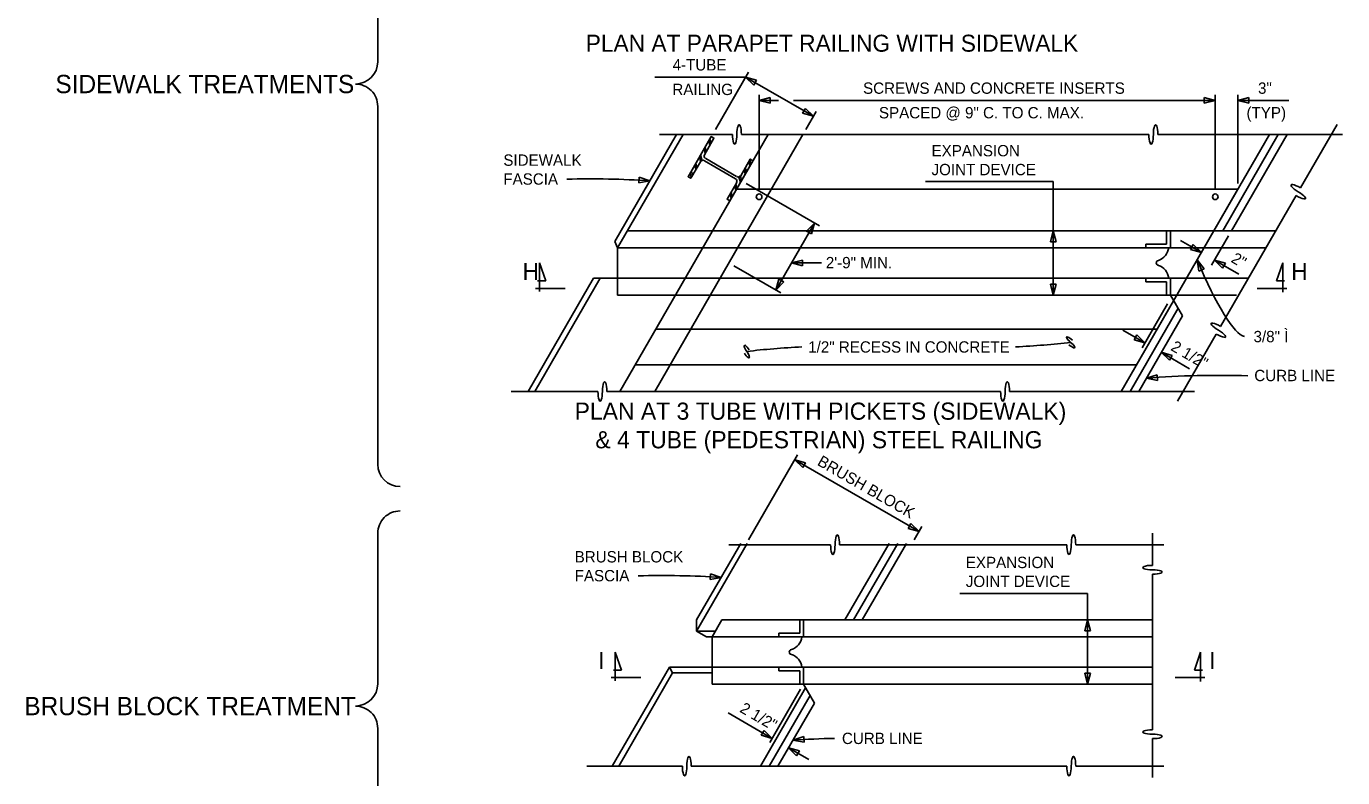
# Model space of a CAD drawing. Extents: x 19590 to 20151, y 19944 to 20103.
# Drawn here: x 19792.8 to 19846.6, y 20034 to 20064.6 of the extents above; entities that cross this region are included whole.
import ezdxf

# ---------------------------------------------------------------- set-up
doc = ezdxf.new("R2010")
doc.units = 0
for name, color, linetype in [('DETAIL_PR', 7, 'Continuous'), ('DETAIL_TEXT_DIMEN_PR', 7, 'Continuous'), ('Level 1', 7, 'Continuous'), ('Sheet_Label_Str_Wt0', 7, 'Continuous')]:
    doc.layers.add(name, color=color, linetype=linetype)

msp = doc.modelspace()

# ---------------------------------------------------------------- linework, layer by layer
at = {"layer": 'DETAIL_PR'}
for p, q in [((19846.336, 20060.613), (19844.846, 20058.032)), ((19819.373, 20060.212), (19816.849, 20055.842)), ((19819.64, 20060.212), (19816.969, 20055.587)), ((19823.111, 20060.212), (19817.058, 20049.729)), ((19824.535, 20060.212), (19818.482, 20049.729)), ((19818.679, 20060.212), (19821.655, 20060.212)), ((19820.781, 20059.853), (19820.734, 20060.025)), ((19822.019, 20060.212), (19838.657, 20060.212)), ((19839.021, 20060.212), (19846.567, 20060.212)), ((19843.583, 20060.212), (19841.313, 20056.281)), ((19843.939, 20060.212), (19841.669, 20056.281)), ((19844.295, 20060.212), (19842.025, 20056.281)), ((19820.542, 20059.439), (19820.501, 20059.622)), ((19820.586, 20059.515), (19820.546, 20059.699)), ((19820.731, 20059.766), (19820.69, 20059.949)), ((19820.164, 20058.784), (19820.123, 20058.968)), ((19820.208, 20058.861), (19820.167, 20059.043)), ((19820.353, 20059.111), (19820.312, 20059.295)), ((19820.417, 20059.147), (19820.357, 20059.371)), ((19821.775, 20058.406), (19820.512, 20059.135)), ((19820.563, 20059.223), (19821.826, 20058.494)), ((19822.32, 20059.096), (19822.361, 20058.912)), ((19822.364, 20059.172), (19822.411, 20058.999)), ((19819.975, 20058.457), (19819.928, 20058.629)), ((19820.019, 20058.533), (19819.978, 20058.717)), ((19821.983, 20058.257), (19821.922, 20058.482)), ((19821.986, 20058.517), (19822.027, 20058.334)), ((19822.131, 20058.768), (19822.172, 20058.585)), ((19822.176, 20058.844), (19822.223, 20058.671)), ((19821.609, 20057.863), (19821.649, 20057.679)), ((19821.754, 20058.114), (19821.794, 20057.93)), ((19821.797, 20058.19), (19821.838, 20058.006)), ((19821.82, 20057.977), (19823.245, 20057.977)), ((19823.245, 20057.977), (19842.292, 20057.977)), ((19842.292, 20057.977), (19838.999, 20052.272)), ((19842.292, 20057.977), (19838.999, 20052.272)), ((19821.558, 20057.776), (19821.605, 20057.603)), ((19844.664, 20057.716), (19841.584, 20052.381)), ((19817.37, 20056.281), (19820.841, 20056.281)), ((19820.841, 20056.281), (19822.265, 20056.281)), ((19822.265, 20056.281), (19841.313, 20056.281)), ((19839.379, 20055.741), (19839.379, 20056.281)), ((19839.533, 20055.587), (19839.533, 20056.281)), ((19841.313, 20056.281), (19843.835, 20056.281)), ((19816.849, 20055.842), (19816.969, 20055.587)), ((19838.531, 20055.587), (19838.531, 20055.741)), ((19838.531, 20055.741), (19839.379, 20055.741)), ((19816.969, 20055.587), (19820.441, 20055.587)), ((19816.969, 20053.66), (19816.969, 20055.587)), ((19817.759, 20055.587), (19818.453, 20055.587)), ((19820.441, 20055.587), (19821.865, 20055.587)), ((19821.865, 20055.587), (19840.913, 20055.587)), ((19840.913, 20055.587), (19843.435, 20055.587)), ((19815.99, 20054.354), (19813.319, 20049.729)), ((19816.257, 20054.354), (19813.587, 20049.729)), ((19815.99, 20054.354), (19816.969, 20054.354)), ((19816.969, 20054.354), (19819.729, 20054.354)), ((19819.729, 20054.354), (19821.153, 20054.354)), ((19821.153, 20054.354), (19840.201, 20054.354)), ((19838.531, 20054.354), (19838.531, 20054.2)), ((19838.531, 20054.199), (19839.379, 20054.199)), ((19839.379, 20054.2), (19839.379, 20053.66)), ((19839.533, 20054.354), (19839.533, 20053.66)), ((19840.201, 20054.354), (19842.723, 20054.354)), ((19816.969, 20053.66), (19819.328, 20053.66)), ((19819.328, 20053.66), (19820.752, 20053.66)), ((19820.752, 20053.66), (19839.8, 20053.66)), ((19839.533, 20053.66), (19840.023, 20052.812)), ((19839.533, 20053.66), (19840.023, 20052.812)), ((19839.8, 20053.66), (19842.233, 20053.66)), ((19839.667, 20053.428), (19837.53, 20049.729)), ((19839.667, 20053.428), (19837.53, 20049.729)), ((19839.845, 20053.12), (19837.886, 20049.729)), ((19839.845, 20053.12), (19837.886, 20049.729)), ((19840.023, 20052.812), (19838.242, 20049.729)), ((19840.023, 20052.812), (19838.242, 20049.729)), ((19818.527, 20052.272), (19819.951, 20052.272)), ((19819.951, 20052.272), (19838.999, 20052.272)), ((19819.951, 20052.272), (19838.999, 20052.272)), ((19841.402, 20052.066), (19839.821, 20049.328)), ((19841.402, 20052.066), (19839.821, 20049.328)), ((19817.681, 20050.808), (19819.105, 20050.808)), ((19819.105, 20050.808), (19838.153, 20050.808)), ((19812.626, 20049.729), (19816.164, 20049.729)), ((19816.528, 20049.729), (19832.605, 20049.729)), ((19832.969, 20049.729), (19840.515, 20049.729)), ((19838.803, 20043.937), (19838.803, 20042.63)), ((19821.996, 20043.528), (19820.193, 20040.406)), ((19822.263, 20043.528), (19820.193, 20039.943)), ((19821.502, 20043.474), (19825.663, 20043.474)), ((19826.027, 20043.474), (19835.307, 20043.474)), ((19828.048, 20043.528), (19826.246, 20040.406)), ((19828.404, 20043.528), (19826.602, 20040.406)), ((19828.76, 20043.528), (19826.958, 20040.406)), ((19835.67, 20043.474), (19839.266, 20043.474)), ((19838.803, 20042.266), (19838.803, 20037.631)), ((19820.193, 20039.943), (19820.193, 20040.406)), ((19821.226, 20040.406), (19820.825, 20039.712)), ((19821.226, 20040.406), (19838.803, 20040.406)), ((19824.4, 20039.866), (19824.4, 20040.406)), ((19824.555, 20039.712), (19824.555, 20040.406)), ((19820.193, 20039.943), (19820.959, 20039.943)), ((19820.193, 20039.943), (19820.594, 20039.712)), ((19820.594, 20039.712), (19820.825, 20039.712)), ((19820.825, 20039.712), (19838.803, 20039.712)), ((19820.825, 20037.785), (19820.825, 20039.712)), ((19823.552, 20039.712), (19823.552, 20039.866)), ((19823.552, 20039.866), (19824.4, 20039.866)), ((19819.081, 20038.479), (19816.748, 20034.438)), ((19819.214, 20038.247), (19817.015, 20034.438)), ((19819.081, 20038.479), (19820.825, 20038.479)), ((19819.214, 20038.247), (19819.081, 20038.479)), ((19819.214, 20038.247), (19820.825, 20038.247)), ((19820.825, 20038.479), (19838.803, 20038.479)), ((19823.552, 20038.479), (19823.552, 20038.324)), ((19823.552, 20038.324), (19824.4, 20038.324)), ((19824.4, 20038.324), (19824.4, 20037.785)), ((19824.555, 20038.479), (19824.555, 20037.785)), ((19820.825, 20037.785), (19838.803, 20037.785)), ((19824.644, 20037.631), (19822.801, 20034.438)), ((19824.555, 20037.785), (19825, 20037.014)), ((19838.803, 20035.924), (19838.803, 20037.631)), ((19824.822, 20037.322), (19823.157, 20034.438)), ((19825, 20037.014), (19823.513, 20034.438)), ((19838.803, 20035.56), (19838.803, 20033.976)), ((19815.717, 20034.438), (19819.611, 20034.438)), ((19819.975, 20034.438), (19835.307, 20034.438)), ((19835.67, 20034.438), (19839.265, 20034.438))]:
    msp.add_line(p, q, dxfattribs=at)
for points in [[(19820.346, 20059.1), (19819.956, 20058.424), (19819.846, 20058.488), (19820.791, 20060.124), (19820.901, 20060.061), (19820.51, 20059.384)], [(19821.993, 20058.528), (19822.383, 20059.204), (19822.493, 20059.141), (19821.548, 20057.506), (19821.438, 20057.568), (19821.829, 20058.245)]]:
    msp.add_lwpolyline(points, dxfattribs=at)
for centre in [(19822.746, 20057.668), (19841.367, 20057.668), (19841.367, 20057.668)]:
    msp.add_circle(centre, 0.116, dxfattribs=at)
for centre, radius, start, end in [((19838.856, 20055.652), 0.612, 288.1365, 353.9316), ((19839.055, 20054.971), 0.0999, 94.4387, 265.5613), ((19838.856, 20054.289), 0.612, 6.0684, 71.8635), ((19823.878, 20039.777), 0.612, 288.1365, 353.9316), ((19824.076, 20039.095), 0.0999, 94.4387, 265.5613), ((19823.878, 20038.414), 0.612, 6.0684, 71.8635)]:
    msp.add_arc(centre, radius, start, end, dxfattribs=at)
for centre, major_axis, ratio, start_param, end_param in [((19821.928, 20060.212), (0, -0.395), 0.230204, 1.570796, 4.712389), ((19838.93, 20060.212), (0, -0.395), 0.230204, 1.570796, 4.712389), ((19821.746, 20060.212), (0, -0.395), 0.230206, 4.712389, 7.853982), ((19838.748, 20060.212), (0, -0.395), 0.230206, 4.712389, 7.853982), ((19820.453, 20059.041), (0.1, -0.058), 0.993605, 1.570796, 3.141593), ((19820.616, 20059.323), (0.1, -0.058), 0.993605, 3.141593, 4.712389), ((19821.724, 20058.306), (0.1, -0.058), 0.993605, 0, 1.570796), ((19821.888, 20058.589), (0.1, -0.058), 0.993605, 4.712389, 6.283185), ((19844.801, 20057.953), (0.342, -0.198), 0.230204, 1.570796, 4.712389), ((19844.71, 20057.795), (0.342, -0.198), 0.230206, 4.712389, 7.853982), ((19841.539, 20052.303), (0.342, -0.198), 0.230204, 1.570796, 4.712389), ((19835.502, 20051.773), (0.203, -0.168), 0.230204, 1.570796, 4.712389), ((19841.448, 20052.145), (0.342, -0.198), 0.230206, 4.712389, 7.853982), ((19822.293, 20051.387), (0.147, -0.219), 0.230204, 1.570796, 4.712389), ((19835.424, 20051.68), (0.203, -0.168), 0.230206, 4.712389, 7.853982), ((19822.192, 20051.32), (0.147, -0.219), 0.230206, 4.712389, 7.853982), ((19816.437, 20049.729), (0, -0.395), 0.230204, 1.570796, 4.712389), ((19832.878, 20049.729), (0, -0.395), 0.230204, 1.570796, 4.712389), ((19816.255, 20049.729), (0, -0.395), 0.230206, 4.712389, 7.853982), ((19832.696, 20049.729), (0, -0.395), 0.230206, 4.712389, 7.853982), ((19825.754, 20043.474), (0, -0.395), 0.230206, 4.712389, 7.853982), ((19825.936, 20043.474), (0, -0.395), 0.230204, 1.570796, 4.712389), ((19835.397, 20043.474), (0, -0.395), 0.230206, 4.712389, 7.853982), ((19835.579, 20043.474), (0, -0.395), 0.230204, 1.570796, 4.712389), ((19838.803, 20042.539), (0.395, 0), 0.230204, 1.570796, 4.712389), ((19838.803, 20042.357), (0.395, 0), 0.230206, 4.712389, 7.853982), ((19838.803, 20035.833), (0.395, 0), 0.230204, 1.570796, 4.712389), ((19838.803, 20035.651), (0.395, 0), 0.230206, 4.712389, 7.853982), ((19819.884, 20034.438), (0, -0.395), 0.230204, 1.570796, 4.712389), ((19835.579, 20034.438), (0, -0.395), 0.230204, 1.570796, 4.712389), ((19819.702, 20034.438), (0, -0.395), 0.230206, 4.712389, 7.853982), ((19835.397, 20034.438), (0, -0.395), 0.230206, 4.712389, 7.853982)]:
    msp.add_ellipse(centre, major_axis=major_axis, ratio=ratio, start_param=start_param, end_param=end_param, dxfattribs=at)
at = {"layer": 'DETAIL_TEXT_DIMEN_PR'}
for p, q in [((19807.176, 20077.779), (19807.176, 20063.131)), ((19820.957, 20060.412), (19822.307, 20062.751)), ((19818.492, 20062.551), (19822.192, 20062.551)), ((19822.192, 20062.551), (19824.962, 20060.951)), ((19822.746, 20057.977), (19822.746, 20061.831)), ((19841.367, 20057.977), (19841.367, 20061.831)), ((19842.292, 20058.208), (19842.292, 20061.831)), ((19807.176, 20061.378), (19807.176, 20046.757)), ((19822.746, 20061.599), (19823.531, 20061.599)), ((19824.148, 20061.599), (19841.367, 20061.599)), ((19824.651, 20060.412), (19825.078, 20061.151)), ((19842.292, 20061.599), (19844.374, 20061.599)), ((19822.221, 20058.208), (19825.209, 20056.483)), ((19829.542, 20058.285), (19834.754, 20058.285)), ((19834.754, 20058.285), (19834.754, 20053.66)), ((19823.429, 20053.862), (19825.008, 20056.598)), ((19840.8, 20055.392), (19839.949, 20055.883)), ((19841.219, 20054.883), (19841.91, 20056.08)), ((19813.78, 20053.799), (19813.78, 20054.97)), ((19813.78, 20054.97), (19814.032, 20054.234)), ((19821.709, 20054.855), (19823.629, 20053.746)), ((19824.069, 20054.97), (19825.294, 20054.97)), ((19841.334, 20055.083), (19842.335, 20054.505)), ((19844.119, 20054.97), (19843.866, 20054.234)), ((19844.118, 20053.772), (19844.119, 20054.97)), ((19814.032, 20054.234), (19813.702, 20054.234)), ((19843.866, 20054.234), (19844.197, 20054.234)), ((19814.82, 20053.93), (19813.614, 20053.93)), ((19843.079, 20053.93), (19844.294, 20053.93)), ((19838.379, 20051.507), (19839.417, 20053.305)), ((19837.594, 20052.228), (19838.495, 20051.707)), ((19839.162, 20051.322), (19840.32, 20050.654)), ((19822.312, 20043.674), (19824.314, 20047.143)), ((19824.198, 20046.942), (19829.272, 20044.013)), ((19807.176, 20043.941), (19807.176, 20037.756)), ((19829.076, 20043.674), (19829.387, 20044.213)), ((19830.941, 20041.485), (19836.153, 20041.485)), ((19836.153, 20041.485), (19836.153, 20037.785)), ((19816.871, 20037.924), (19816.87, 20039.095)), ((19816.87, 20039.095), (19817.123, 20038.359)), ((19840.768, 20039.095), (19840.515, 20038.359)), ((19840.768, 20037.897), (19840.768, 20039.095)), ((19817.911, 20038.055), (19816.705, 20038.055)), ((19817.123, 20038.359), (19816.793, 20038.359)), ((19839.728, 20038.055), (19840.943, 20038.055)), ((19840.515, 20038.359), (19840.846, 20038.359)), ((19823.178, 20035.4), (19824.439, 20037.585)), ((19821.475, 20036.614), (19823.278, 20035.573)), ((19807.176, 20035.98), (19807.176, 20029.838)), ((19823.945, 20035.188), (19824.773, 20034.71))]:
    msp.add_line(p, q, dxfattribs=at)
for centre, radius, start, end in [((19806.266, 20063.179), 0.911, 269.9663, 359.9663), ((19806.266, 20061.358), 0.91, 359.9663, 90.0337), ((19815.856, 20019.247), 39.151, 86.4465, 91.4029), ((19841.537, 20011.231), 39.151, 88.2954, 94.3693), ((19841.537, 20011.231), 39.151, 88.2954, 94.3693), ((19808.086, 20046.758), 0.91, 180.0337, 270.0337), ((19808.086, 20043.941), 0.91, 89.9663, 180.0337), ((19818.768, 20003.064), 39.151, 86.4465, 91.4029), ((19806.266, 20037.8), 0.911, 269.9663, 359.9663), ((19806.266, 20035.98), 0.91, 359.9663, 90.0337), ((19826.554, 19996.426), 39.151, 91.0778, 93.5535)]:
    msp.add_arc(centre, radius, start, end, dxfattribs=at)
at = {"layer": 'Level 1'}
for p, q in [((19822.192, 20062.551), (19822.522, 20062.226)), ((19822.638, 20062.426), (19822.192, 20062.551)), ((19822.522, 20062.226), (19822.638, 20062.426)), ((19822.746, 20061.599), (19823.194, 20061.715)), ((19823.194, 20061.715), (19823.194, 20061.484)), ((19841.367, 20061.599), (19840.919, 20061.715)), ((19840.919, 20061.715), (19840.919, 20061.484)), ((19842.292, 20061.599), (19842.74, 20061.715)), ((19842.74, 20061.715), (19842.74, 20061.484)), ((19823.194, 20061.484), (19822.746, 20061.599)), ((19824.517, 20061.075), (19824.632, 20061.275)), ((19824.632, 20061.275), (19824.962, 20060.951)), ((19840.919, 20061.484), (19841.367, 20061.599)), ((19842.74, 20061.484), (19842.292, 20061.599)), ((19824.962, 20060.951), (19824.517, 20061.075)), ((19817.828, 20058.233), (19817.842, 20058.464)), ((19817.842, 20058.464), (19818.282, 20058.323)), ((19818.282, 20058.323), (19817.828, 20058.233)), ((19824.684, 20056.268), (19825.008, 20056.598)), ((19824.885, 20056.152), (19824.684, 20056.268)), ((19825.008, 20056.598), (19824.885, 20056.152)), ((19834.638, 20055.833), (19834.754, 20056.281)), ((19834.754, 20056.281), (19834.87, 20055.833)), ((19834.87, 20055.833), (19834.638, 20055.833)), ((19840.354, 20055.515), (19840.47, 20055.716)), ((19840.47, 20055.716), (19840.8, 20055.392)), ((19840.8, 20055.392), (19840.354, 20055.515)), ((19824.069, 20054.97), (19824.517, 20055.086)), ((19824.517, 20054.855), (19824.069, 20054.97)), ((19824.517, 20055.086), (19824.517, 20054.855)), ((19840.628, 20055.093), (19840.911, 20054.727)), ((19840.698, 20054.636), (19840.628, 20055.093)), ((19840.911, 20054.727), (19840.698, 20054.636)), ((19841.334, 20055.083), (19841.664, 20054.759)), ((19841.78, 20054.959), (19841.334, 20055.083)), ((19841.664, 20054.759), (19841.78, 20054.959)), ((19823.553, 20054.308), (19823.429, 20053.862)), ((19823.429, 20053.862), (19823.753, 20054.193)), ((19823.753, 20054.193), (19823.553, 20054.308)), ((19834.869, 20054.108), (19834.638, 20054.108)), ((19834.638, 20054.108), (19834.754, 20053.66)), ((19834.754, 20053.66), (19834.869, 20054.108)), ((19838.049, 20051.831), (19838.164, 20052.031)), ((19838.164, 20052.031), (19838.495, 20051.707)), ((19838.495, 20051.707), (19838.049, 20051.831)), ((19839.608, 20051.198), (19839.162, 20051.322)), ((19839.162, 20051.322), (19839.492, 20050.998)), ((19839.492, 20050.998), (19839.608, 20051.198)), ((19838.554, 20050.269), (19838.995, 20050.409)), ((19838.995, 20050.409), (19839.008, 20050.178)), ((19839.008, 20050.178), (19838.554, 20050.269)), ((19824.198, 20046.942), (19824.528, 20046.618)), ((19824.644, 20046.818), (19824.198, 20046.942)), ((19824.528, 20046.618), (19824.644, 20046.818)), ((19828.942, 20044.337), (19828.826, 20044.137)), ((19828.826, 20044.137), (19829.272, 20044.013)), ((19829.272, 20044.013), (19828.942, 20044.337)), ((19820.754, 20042.28), (19820.741, 20042.049)), ((19821.195, 20042.14), (19820.754, 20042.28)), ((19820.741, 20042.049), (19821.195, 20042.14)), ((19836.037, 20039.958), (19836.153, 20040.406)), ((19836.153, 20040.406), (19836.269, 20039.958)), ((19836.269, 20039.958), (19836.037, 20039.958)), ((19836.268, 20038.233), (19836.037, 20038.233)), ((19836.037, 20038.233), (19836.153, 20037.785)), ((19836.153, 20037.785), (19836.268, 20038.233)), ((19822.832, 20035.697), (19822.947, 20035.897)), ((19822.947, 20035.897), (19823.278, 20035.573)), ((19823.278, 20035.573), (19822.832, 20035.697)), ((19824.568, 20035.643), (19824.127, 20035.502)), ((19824.127, 20035.502), (19824.581, 20035.412)), ((19824.581, 20035.412), (19824.568, 20035.643)), ((19823.945, 20035.187), (19824.391, 20035.064)), ((19824.275, 20034.863), (19823.945, 20035.187)), ((19824.391, 20035.064), (19824.275, 20034.863))]:
    msp.add_line(p, q, dxfattribs=at)
for centre, major_axis, start_param, end_param in [((19840.661, 20058.235), (2.009, -6.26), 5.183087, 6.19004), ((19825.145, 20050.456), (-6.57, -0.223), 4.805942, 5.164147), ((19832.561, 20052.63), (6.57, 0.223), 4.805942, 5.164147)]:
    msp.add_ellipse(centre, major_axis=major_axis, ratio=0.169331, start_param=start_param, end_param=end_param, dxfattribs=at)

# ---------------------------------------------------------------- texts
at = {"layer": 'DETAIL_TEXT_DIMEN_PR'}
for s, height, p in [('PLAN AT PARAPET RAILING WITH SIDEWALK', 0.69385, (19815.665, 20063.586)), ('4-TUBE', 0.4625, (19819.212, 20062.82)), ('RAILING', 0.4625, (19819.203, 20061.818)), ('SCREWS AND CONCRETE INSERTS', 0.4625, (19826.988, 20061.869)), ('3"', 0.4625, (19843.112, 20061.869)), ('SPACED @ 9" C. TO C. MAX.', 0.4625, (19827.636, 20060.867)), ('(TYP)', 0.4625, (19842.641, 20060.867)), ('EXPANSION ', 0.4625, (19829.783, 20059.318)), ('SIDEWALK', 0.4625, (19812.302, 20058.932)), ('JOINT DEVICE', 0.4625, (19829.783, 20058.547)), ('FASCIA', 0.4625, (19812.302, 20058.161)), ('2\'-9" MIN.', 0.4625, (19825.468, 20054.75)), ('H', 0.694, (19813.086, 20054.277)), ('H', 0.694, (19844.466, 20054.277)), ('1/2" RECESS IN CONCRETE', 0.4625, (19824.748, 20051.309)), ('CURB LINE', 0.4625, (19842.96, 20050.145)), ('PLAN AT 3 TUBE WITH PICKETS (SIDEWALK)', 0.69987, (19815.213, 20048.572)), (' & 4 TUBE (PEDESTRIAN) STEEL RAILING', 0.69987, (19815.799, 20047.406)), ('BRUSH BLOCK', 0.4625, (19815.214, 20042.749)), ('EXPANSION ', 0.4625, (19831.182, 20042.518)), ('FASCIA', 0.4625, (19815.214, 20041.978)), ('JOINT DEVICE', 0.4625, (19831.182, 20041.747)), ('I', 0.694, (19816.177, 20038.402)), ('I', 0.694, (19841.115, 20038.402)), ('CURB LINE', 0.4625, (19826.126, 20035.34))]:
    msp.add_text(s, height=height, dxfattribs=at).set_placement(p)
for s, height, rotation, p in [('SIDEWALK TREATMENTS', 0.74643, 360, (19794.015, 20061.895)), ('2"', 0.4625, 330, (19841.976, 20055.025)), ('2 1/2"', 0.4625, 330, (19839.513, 20051.428)), ('BRUSH BLOCK', 0.4625, 330, (19825.084, 20046.743)), ('BRUSH BLOCK TREATMENT', 0.74643, 360, (19792.747, 20036.516)), ('2 1/2"', 0.4625, 330, (19821.921, 20036.669))]:
    msp.add_text(s, height=height, rotation=rotation, dxfattribs=at).set_placement(p)
at = {"layer": 'Sheet_Label_Str_Wt0'}
msp.add_text('3/8" Ì', height=0.4625, dxfattribs=at).set_placement((19842.928, 20051.734))

doc.saveas('drawing.dxf')
